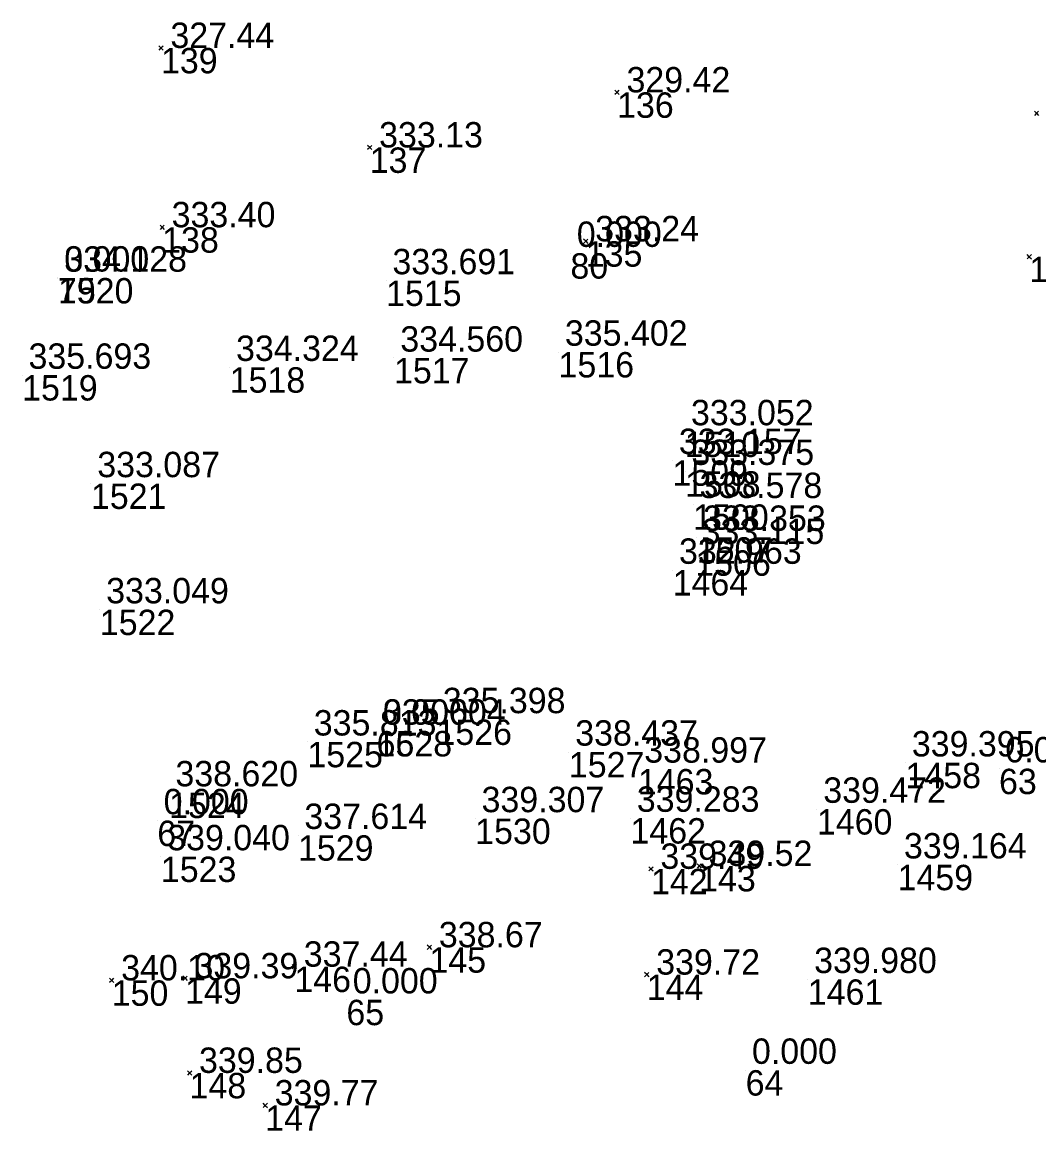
# Model space of a CAD drawing. Extents: x -829398 to -819400, y -1074439 to -1067977.
# Drawn here: x -826013.4 to -825965.4, y -1070173.3 to -1070120.9 of the extents above; entities that cross this region are included whole.
import ezdxf

# ---------------------------------------------------------------- set-up
doc = ezdxf.new("R2010")
doc.units = 0
doc.layers.add('Vrstva 60', color=7, linetype='Continuous')
doc.layers.add('Vrstva 61', color=7, linetype='Continuous')

msp = doc.modelspace()

# ---------------------------------------------------------------- linework, layer by layer
at = {"layer": 'Vrstva 60'}
for p, q in [((-826006.864, -1070122.161), (-826006.964, -1070122.061)), ((-826006.864, -1070122.161), (-826006.964, -1070122.261)), ((-826006.864, -1070122.161), (-826006.764, -1070122.061)), ((-826006.864, -1070122.161), (-826006.764, -1070122.261)), ((-825985.3, -1070124.263), (-825985.4, -1070124.163)), ((-825985.3, -1070124.263), (-825985.4, -1070124.363)), ((-825985.3, -1070124.263), (-825985.2, -1070124.163)), ((-825985.3, -1070124.263), (-825985.2, -1070124.363)), ((-825965.47, -1070125.248), (-825965.57, -1070125.148)), ((-825965.47, -1070125.248), (-825965.57, -1070125.348)), ((-825965.47, -1070125.248), (-825965.37, -1070125.148)), ((-825965.47, -1070125.248), (-825965.37, -1070125.348)), ((-825996.997, -1070126.866), (-825997.097, -1070126.766)), ((-825996.997, -1070126.866), (-825997.097, -1070126.966)), ((-825996.997, -1070126.866), (-825996.897, -1070126.766)), ((-825996.997, -1070126.866), (-825996.897, -1070126.966)), ((-826006.807, -1070130.637), (-826006.907, -1070130.537)), ((-826006.807, -1070130.637), (-826006.907, -1070130.737)), ((-826006.807, -1070130.637), (-826006.707, -1070130.537)), ((-826006.807, -1070130.637), (-826006.707, -1070130.737)), ((-825986.78, -1070131.3), (-825986.88, -1070131.2)), ((-825986.78, -1070131.3), (-825986.88, -1070131.4)), ((-825986.78, -1070131.3), (-825986.68, -1070131.2)), ((-825986.78, -1070131.3), (-825986.68, -1070131.4)), ((-825987.505, -1070131.865), (-825987.505, -1070131.865)), ((-825965.811, -1070132.029), (-825965.911, -1070131.929)), ((-825965.811, -1070132.029), (-825965.911, -1070132.129)), ((-825965.811, -1070132.029), (-825965.711, -1070131.929)), ((-825965.811, -1070132.029), (-825965.711, -1070132.129)), ((-826011.737, -1070133.032), (-826011.737, -1070133.032)), ((-826011.737, -1070133.038), (-826011.737, -1070133.038)), ((-825996.221, -1070133.158), (-825996.221, -1070133.158)), ((-825988.067, -1070136.536), (-825988.067, -1070136.536)), ((-825995.848, -1070136.816), (-825995.848, -1070136.816)), ((-826013.428, -1070137.627), (-826013.428, -1070137.627)), ((-826003.615, -1070137.255), (-826003.615, -1070137.255)), ((-825982.107, -1070140.296), (-825982.107, -1070140.296)), ((-825982.678, -1070141.656), (-825982.678, -1070141.656)), ((-825982.085, -1070142.17), (-825982.085, -1070142.17)), ((-826010.176, -1070142.75), (-826010.176, -1070142.75)), ((-825981.701, -1070143.737), (-825981.701, -1070143.737)), ((-825981.534, -1070145.288), (-825981.534, -1070145.288)), ((-825981.603, -1070145.909), (-825981.603, -1070145.909)), ((-825982.672, -1070146.845), (-825982.672, -1070146.845)), ((-826009.755, -1070148.713), (-826009.755, -1070148.713)), ((-825993.839, -1070153.905), (-825993.839, -1070153.905)), ((-825996.671, -1070154.451), (-825996.671, -1070154.451)), ((-825996.67, -1070154.448), (-825996.67, -1070154.448)), ((-825999.941, -1070154.961), (-825999.941, -1070154.961)), ((-825987.579, -1070155.44), (-825987.579, -1070155.44)), ((-825971.663, -1070155.951), (-825971.663, -1070155.951)), ((-825984.315, -1070156.243), (-825984.315, -1070156.243)), ((-825967.241, -1070156.232), (-825967.241, -1070156.232)), ((-826006.482, -1070157.363), (-826006.482, -1070157.363)), ((-825992.008, -1070158.585), (-825992.008, -1070158.585)), ((-825984.667, -1070158.567), (-825984.667, -1070158.567)), ((-825975.851, -1070158.142), (-825975.851, -1070158.142)), ((-826007.038, -1070158.683), (-826007.038, -1070158.683)), ((-826000.386, -1070159.378), (-826000.386, -1070159.378)), ((-826006.869, -1070160.385), (-826006.869, -1070160.385)), ((-825983.697, -1070160.963), (-825983.797, -1070160.863)), ((-825983.697, -1070160.963), (-825983.797, -1070161.063)), ((-825983.697, -1070160.963), (-825983.597, -1070160.863)), ((-825983.697, -1070160.963), (-825983.597, -1070161.063)), ((-825981.42, -1070160.827), (-825981.52, -1070160.727)), ((-825981.42, -1070160.827), (-825981.52, -1070160.927)), ((-825981.42, -1070160.827), (-825981.32, -1070160.727)), ((-825981.42, -1070160.827), (-825981.32, -1070160.927)), ((-825972.037, -1070160.773), (-825972.037, -1070160.773)), ((-825994.172, -1070164.671), (-825994.272, -1070164.571)), ((-825994.172, -1070164.671), (-825994.272, -1070164.771)), ((-825994.172, -1070164.671), (-825994.072, -1070164.571)), ((-825994.172, -1070164.671), (-825994.072, -1070164.771)), ((-826000.558, -1070165.587), (-826000.658, -1070165.487)), ((-826000.558, -1070165.587), (-826000.658, -1070165.687)), ((-826000.558, -1070165.587), (-826000.458, -1070165.487)), ((-826000.558, -1070165.587), (-826000.458, -1070165.687)), ((-825983.896, -1070165.962), (-825983.996, -1070165.862)), ((-825983.896, -1070165.962), (-825983.796, -1070165.862)), ((-826009.193, -1070166.236), (-826009.293, -1070166.136)), ((-826009.193, -1070166.236), (-826009.293, -1070166.336)), ((-826009.193, -1070166.236), (-826009.093, -1070166.136)), ((-826009.193, -1070166.236), (-826009.093, -1070166.336)), ((-826005.725, -1070166.138), (-826005.825, -1070166.038)), ((-826005.725, -1070166.138), (-826005.825, -1070166.238)), ((-826005.725, -1070166.138), (-826005.625, -1070166.038)), ((-826005.725, -1070166.138), (-826005.625, -1070166.238)), ((-825983.896, -1070165.962), (-825983.996, -1070166.062)), ((-825983.896, -1070165.962), (-825983.796, -1070166.062)), ((-825976.282, -1070166.188), (-825976.282, -1070166.188)), ((-825998.098, -1070167.152), (-825998.098, -1070167.152)), ((-826005.513, -1070170.608), (-826005.613, -1070170.508)), ((-826005.513, -1070170.608), (-826005.613, -1070170.708)), ((-826005.513, -1070170.608), (-826005.413, -1070170.508)), ((-826005.513, -1070170.608), (-826005.413, -1070170.708)), ((-825979.221, -1070170.48), (-825979.221, -1070170.48)), ((-826001.935, -1070172.146), (-826002.035, -1070172.046)), ((-826001.935, -1070172.146), (-826002.035, -1070172.246)), ((-826001.935, -1070172.146), (-826001.835, -1070172.046)), ((-826001.935, -1070172.146), (-826001.835, -1070172.246))]:
    msp.add_line(p, q, dxfattribs=at)

# ---------------------------------------------------------------- texts
for s, p in [('139', (-826006.864, -1070123.361)), ('136', (-825985.3, -1070125.463)), ('137', (-825996.997, -1070128.066)), ('138', (-826006.807, -1070131.837)), ('135', (-825986.78, -1070132.5)), ('80', (-825987.505, -1070133.065)), ('134', (-825965.811, -1070133.229)), ('79', (-826011.737, -1070134.232)), ('1520', (-826011.737, -1070134.238)), ('1515', (-825996.221, -1070134.358)), ('1516', (-825988.067, -1070137.736)), ('1517', (-825995.848, -1070138.016)), ('1519', (-826013.428, -1070138.827)), ('1518', (-826003.615, -1070138.455)), ('1510', (-825982.107, -1070141.496)), ('1509', (-825982.678, -1070142.856)), ('1508', (-825982.085, -1070143.37)), ('1521', (-826010.176, -1070143.95)), ('1500', (-825981.701, -1070144.937)), ('1507', (-825981.534, -1070146.488)), ('1506', (-825981.603, -1070147.109)), ('1464', (-825982.672, -1070148.045)), ('1522', (-826009.755, -1070149.913)), ('1526', (-825993.839, -1070155.105)), ('1525', (-825999.941, -1070156.161)), ('66', (-825996.671, -1070155.651)), ('1528', (-825996.67, -1070155.648)), ('1527', (-825987.579, -1070156.64)), ('1458', (-825971.663, -1070157.151)), ('1463', (-825984.315, -1070157.443)), ('63', (-825967.241, -1070157.432)), ('1524', (-826006.482, -1070158.563)), ('1530', (-825992.008, -1070159.785)), ('1462', (-825984.667, -1070159.767)), ('1460', (-825975.851, -1070159.342)), ('67', (-826007.038, -1070159.883)), ('1529', (-826000.386, -1070160.578)), ('1523', (-826006.869, -1070161.585)), ('142', (-825983.697, -1070162.163)), ('143', (-825981.42, -1070162.027)), ('1459', (-825972.037, -1070161.973)), ('145', (-825994.172, -1070165.871)), ('146', (-826000.558, -1070166.787)), ('150', (-826009.193, -1070167.436)), ('149', (-826005.725, -1070167.338)), ('144', (-825983.896, -1070167.162)), ('1461', (-825976.282, -1070167.388)), ('65', (-825998.098, -1070168.352)), ('148', (-826005.513, -1070171.808)), ('64', (-825979.221, -1070171.68)), ('147', (-826001.935, -1070173.346))]:
    msp.add_text(s, height=1.2, dxfattribs=at).set_placement(p)
at = {"layer": 'Vrstva 61'}
for s, p in [(' 327.44', (-826006.864, -1070122.161)), (' 329.42', (-825985.3, -1070124.263)), (' 333.13', (-825996.997, -1070126.866)), (' 333.40', (-826006.807, -1070130.637)), (' 333.24', (-825986.78, -1070131.3)), ('0.000', (-825987.205, -1070131.565)), ('334.128', (-826011.437, -1070132.738)), ('0.000', (-826011.437, -1070132.732)), ('333.691', (-825995.921, -1070132.858)), ('335.402', (-825987.767, -1070136.236)), ('334.560', (-825995.548, -1070136.516)), ('334.324', (-826003.315, -1070136.955)), ('335.693', (-826013.128, -1070137.327)), ('333.052', (-825981.807, -1070139.996)), ('333.157', (-825982.378, -1070141.356)), ('333.375', (-825981.785, -1070141.87)), ('333.087', (-826009.876, -1070142.45)), ('333.578', (-825981.401, -1070143.437)), ('333.353', (-825981.234, -1070144.988)), ('333.115', (-825981.303, -1070145.609)), ('332.963', (-825982.372, -1070146.545)), ('333.049', (-826009.455, -1070148.413)), ('335.398', (-825993.539, -1070153.605)), ('335.604', (-825996.37, -1070154.148)), ('0.000', (-825996.371, -1070154.151)), ('335.813', (-825999.641, -1070154.661)), ('338.437', (-825987.279, -1070155.14)), ('338.997', (-825984.015, -1070155.943)), ('339.395', (-825971.363, -1070155.651)), ('0.000', (-825966.941, -1070155.932)), ('338.620', (-826006.182, -1070157.063)), ('339.472', (-825975.551, -1070157.842)), ('0.000', (-826006.738, -1070158.383)), ('339.307', (-825991.708, -1070158.285)), ('339.283', (-825984.367, -1070158.267)), ('337.614', (-826000.086, -1070159.078)), ('339.040', (-826006.569, -1070160.085)), (' 339.52', (-825981.42, -1070160.827)), ('339.164', (-825971.737, -1070160.473)), (' 339.49', (-825983.697, -1070160.963)), (' 338.67', (-825994.172, -1070164.671)), (' 337.44', (-826000.558, -1070165.587)), (' 339.72', (-825983.896, -1070165.962)), ('339.980', (-825975.982, -1070165.888)), (' 340.10', (-826009.193, -1070166.236)), (' 339.39', (-826005.725, -1070166.138)), ('0.000', (-825997.798, -1070166.852)), ('0.000', (-825978.921, -1070170.18)), (' 339.85', (-826005.513, -1070170.608)), (' 339.77', (-826001.935, -1070172.146))]:
    msp.add_text(s, height=1.2, dxfattribs=at).set_placement(p)

doc.saveas('drawing.dxf')
